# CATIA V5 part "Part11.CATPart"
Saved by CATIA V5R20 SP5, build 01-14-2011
Part number: Part1
Material "Bronze": density 8860 kg/m3, Young's modulus 1.1e+11 Pa, Poisson ratio 0.341, thermal expansion 1.78e-05 1/K
Material "Bronze": density 8860 kg/m3, Young's modulus 1.1e+11 Pa, Poisson ratio 0.341, thermal expansion 1.78e-05 1/K
Material "Bronze": density 8860 kg/m3, Young's modulus 1.1e+11 Pa, Poisson ratio 0.341, thermal expansion 1.78e-05 1/K
Material "Bronze": density 8860 kg/m3, Young's modulus 1.1e+11 Pa, Poisson ratio 0.341, thermal expansion 1.78e-05 1/K
Bounding box of the stored display mesh (mm): x -25 to 25, y -26 to 25, z -60 to 50
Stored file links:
  E:\Part11.CATPart
  C:\Program Files\Dassault Systemes\B20\intel_a\startup\materials\Catalog.CATMaterial
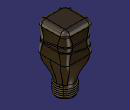
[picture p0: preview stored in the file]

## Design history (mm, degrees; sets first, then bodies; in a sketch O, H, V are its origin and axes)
Set1
  Sketch1 on xy-plane, origin (0, 0, 0), H (1, 0, 0), V (0, 1, 0)
    line L1 (25, 25) -> (25, -25)
    line L2 (25, -25) -> (-25, -25)
    line L3 (-25, -25) -> (-25, 25)
    line L4 (-25, 25) -> (25, 25)
    length L4 = 50
    length L1 = 50
    vertical: L1 V, L3 V
    horizontal: L2 H, L4 H
    equidistance: L1 L3 O, L2 L4 O
  Sketch2 on face of Pad1 from Sketch1.L3, origin (-25, 0, 0), H (0, -1, 0), V (0, 0, 1)
    spline S1 through (-50, 10) (-13.0259, 25.8877) (12.245, 21.8387) (40, 30)
  Extrude1: Element1 Sketch2, Lim1 50, Lim2 10
  MultiSel1: CommonCtxFeats ({extract ExtractElem face of Pad1 from Sketch1.L3}; {extract ExtractElem face of Fillet1}; {extract ExtractElem face of Pad1 from Sketch1.L4}; {extract ExtractElem face of Fillet1}; {extract ExtractElem face of Pad1 from Sketch1.L1}; {extract ExtractElem face of Fillet1}; {extract ExtractElem face of Pad1 from Sketch1.L2}; {extract ExtractElem face of Fillet1})
  Sketch3 on face of Pad1 from Sketch1.L4, origin (0, 25, 0), H (-1, 0, 0), V (0, 0, 1)
    spline S1 through (-50, 10) (-13.9244, 17.0555) (14.8307, 11.3627) (40, 20)
  Extrude2: Element1 Sketch3, Lim1 50, Lim2 74
  MultiSel2: CommonCtxFeats ({extract ExtractElem face of Pad1 from Sketch1.L3}; {extract ExtractElem face of Fillet1}; {extract ExtractElem face of Pad1 from Sketch1.L4}; {extract ExtractElem face of Fillet1}; {extract ExtractElem face of Pad1 from Sketch1.L1}; {extract ExtractElem face of Fillet1}; {extract ExtractElem face of Pad1 from Sketch1.L2}; {extract ExtractElem face of Fillet1})
  Plane1: type OffsetPt, RefPlane face of Pad1 from Sketch1.L1, RefPoint vertex of MultiSel2
  Circle1: type CtrRad, Start 0, End 180, Center vertex of MultiSel2, Support Plane1, Radius 1, FirstDirection (0, -1, 0)
  Circle2: type CtrRad, Start 0, End 180, Center vertex of MultiSel2, Support Plane1, Radius 1, FirstDirection (0, -1, 0)
Body1 (main body), material "Bronze"
  Pad1: profile Sketch1, direction (0, 0, 1), length 50
  Fillet1: on edge [face of Pad1 from Sketch1.L4 | face of Pad1 from Sketch1.L1]; edge [face of Pad1 from Sketch1.L3 | face of Pad1 from Sketch1.L4]; edge [face of Pad1 from Sketch1.L1 | face of Pad1 from Sketch1.L2]; edge [face of Pad1 from Sketch1.L2 | face of Pad1 from Sketch1.L3]
  Fillet2: radius 8, on end face of Pad1
  Plane2: type Offset, RefPlane xy-plane, Offset 40, reversed
  Sketch4 on Plane2, origin (0, 0, -40), H (1, 0, 0), V (0, 1, 0)
    circle A1 centre (0, 0) radius 15
    radius A1 = 15
  Pad2: profile Sketch4, direction (0, 0, -1), length 20
  Sketch5 on start face of Pad1, origin (0, 0, 0), H (1, 0, 0), V (0, -1, 0)
    point P1 (25, 0)
    distance P1 O = 25
  Sketch6 on start face of Pad2, origin (0, 0, -40), H (1, 0, 0), V (0, 1, 0)
    point P1 (15, 0)
    distance P1 O = 15
  Loft1: solid, Sections ({boundary Boundary {extract ExtractElem start face of Pad2}}; {boundary Boundary {extract ExtractElem start face of Pad1}}), StartFace start face of Pad2, EndFace start face of Pad1
  Slot1: profile Circle1, centre curve {join Elements ({intersect ToIntersect2 Extrude2}; {intersect ToIntersect2 Extrude2}; {intersect ToIntersect2 Extrude2}; {intersect ToIntersect2 Extrude2}; {intersect ToIntersect2 Extrude2}; {intersect ToIntersect2 Extrude2}; {intersect ToIntersect2 Extrude2}; {intersect ToIntersect2 Extrude2})}
  Plane3: type OffsetPt, RefPlane face of Pad1 from Sketch1.L1, RefPoint vertex of MultiSel1
  Circle3: type CtrRad, Start 0, End 180, Center vertex of MultiSel1, Support Plane3, Radius 1, FirstDirection (0, -1, 0)
  Slot2: profile Circle3, centre curve {join Elements ({intersect ToIntersect2 Extrude1}; {intersect ToIntersect2 Extrude1}; {intersect ToIntersect2 Extrude1}; {intersect ToIntersect2 Extrude1}; {intersect ToIntersect2 Extrude1}; {intersect ToIntersect2 Extrude1}; {intersect ToIntersect2 Extrude1}; {intersect ToIntersect2 Extrude1})}
  Shell1: ExtOffset 0, Face end face of Pad2, IntOffset 2
  Plane4: type Offset, RefPlane Plane2, Offset 2, reversed
  Sketch7 on Plane4, origin (0, 0, -42), H (1, 0, 0), V (0, 1, 0)
    point P1 (13.7787, -5.9286)
    distance P1 O = 15
Body2, material "Bronze"
  Sketch8 on face of Pad1 from Sketch1.L2, origin (0, -25, 0), H (1, 0, 0), V (0, 0, 1)
    polyline C1
    polyline C2
    polyline C3
    polyline C4
    polyline C5
    polyline C6
    polyline C7
    polyline C8
    polyline C9
    polyline C10
    polyline C11
  Sketch9 on Plane4, origin (0, 0, -42), H (1, 0, 0), V (0, 1, 0)
    point P1 (11.7951, 9.2669)
    distance P1 O = 15
  Helix1: Direction Z axis, RefPoint Sketch9, Pitch 3, Height 16, TaperAngle 0
  Point1: type OnCurve, Support Helix1, Length 5
  Line1: type PtDir, RefPoint Sketch9, Direction (1, 0, 0), Start 0, End 10
  Connect1: Curve1 Line1, Point1 vertex of Line1, Tension1 1, Curve2 Helix1, Point2 Point1, Tension2 1
  Point2: type OnCurve, Support Connect1, RefPoint vertex of Helix1, Length -5.086
  Line2: type PtDir, RefPoint vertex of Helix1, Direction (0, 1, 0), Start 0, End 5
  Connect2: Curve1 Line2, Point1 vertex of Line2, Tension1 1, Curve2 Connect1, Point2 Point2, Tension2 1
  Plane5: type Normal, Curve Connect2, RefPoint vertex of Connect1
  Sketch10 on Plane5, origin (1.7951, 0, 0), H (0, 1, 0), V (0, 0, 1)
    circle A1 centre (9.6014, -42.0724) radius 1
  Rib1: profile Sketch10, centre curve Connect2
  Sketch11 on end face of Pad2, origin (0, 0, -60), H (1, 0, 0), V (0, -1, 0)
    circle A1 centre (0, 0) radius 13.02
    point P1 (13.02, 0)
    distance O A1 = 13.02
    coincidence: A1 P1, P1 H
  Pocket1: profile Sketch11, direction (0, 0, 1), length 20
  Pad3: profile Sketch8, direction (0, -1, 0), length 1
